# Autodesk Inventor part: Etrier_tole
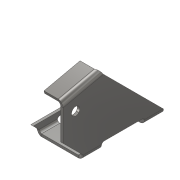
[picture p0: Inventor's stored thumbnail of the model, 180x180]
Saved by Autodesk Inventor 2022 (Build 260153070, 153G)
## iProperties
Created: 2018-06
Part Number: Etrier_tole
Material: Acier inoxydable
Document SubType Name: Tôle
Designer: Fabian Perrée
Density: 8 g/cm^3
Sheet Metal Rule: Par défaut_mm
Appearance: Semi-poli
Flat Pattern Width: 6.40181 cm
Flat Pattern Length: 9.4026 cm
Flat Pattern Area: 60.1936 cm^2
Sheet Metal Width: 64,018 mm
Sheet Metal Length: 94,026 mm
Sheet Metal Area: 6019,365 mm^2
Mass: 45.3586 g
Surface Area: 83.174 cm^2
Volume: 5.66982 cm^3
Author: Fabian Perrée
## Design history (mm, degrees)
node "Face1"
  sketch "Esquisse1"
    geometry: L1 (-12.5, 24)-(12.5, 24); L2 (12.5, 24)-(12.5, -24); L3 (12.5, -24)-(-12.5, -24); L4 (-12.5, -24)-(-12.5, 24); L5 (-12.5, 24)-(12.5, -24); L6 (12.5, 24)-(-12.5, -24); C1 r 3 at (0, 18.5); C2 r 3 at (0, -18.5); 3 further points
    constraints: 12 end point, 4 midpoint, 2 centre point, 2 parallel, 2 vertical alignment, 1 equal radius, 1 horizontal, 1 perpendicular
    dimensions: "d0" = 25 distance of L2.end L3.end; "d1" = 48 distance of L1.end L2.end; "d31" = 5.5 distance from line of L1 C1.centre (= d43); "d32" = 6 diameter of C1; "d43" = 5.5 distance from line of L3 C2.centre
node "Face2"
  sketch "Esquisse2"
    geometry: L1 (0, 0)-(0, 1.5) reference; L2 (48, 0)-(0, 0) reference; L3 (48, 0)-(48, 1.5) reference; L4 (0, 1.5)-(0, 3); L5 (0, 3)-(-12, 15); L6 (-12, 15)-(-12, 36.58); L7 (7, 3.333)-(7, -2.476); L8 (-12, 36.58)-(9.626, 41.374); L9 (48, 1.5)-(48, 3); L10 (48, 3)-(9.626, 41.374); C1 r 2.5 at (-4.5, 28); 2 further points
    constraints: 14 end point, 3 vertical, 1 centre point, 1 coincident, 1 parallel
    dimensions: "d3" = 3 distance from line of L2 L4.end; "d6" = 45 deg angle of L5 L6; "d7" = 28 distance from line of L2 point (-4.5, 28); "d8" = 7 distance between parallel lines of L4 L7; "d9" = 11.5 distance from line of point (-4.5, 28) L7; "d10" = 10 distance from line of point (-4.5, 28) L8; "d11" = 12.5 deg angle of L2 L8; "d12" = 3 distance from line of L2 L9.end; "d13" = 45 deg angle of L2 L10; "d14" = 5 diameter of C1; "d40" = 12 horizontal distance of L5.end L4.end
mirror "Symétrie1"
node "Bord tombé1"
sketch "Esquisse4"
  geometry: L1 (0, 0)-(48, 0) reference; L2 (11, 0)-(37, 0); L3 (37, 0)-(37, 2.5); L4 (35.5, 4)-(12.5, 4); L5 (11, 2.5)-(11, 0); L6 (2.5, 1.5)-(8.5, 1.5) reference; L7 (8.5, 0)-(2.5, 0) reference; L8 (0, 1.5)-(48, 1.5) reference; L9 (8.5, 0)-(2.5, 0) reference; L10 (45.5, 0)-(39.5, 0) reference; L11 (5.5, 0)-(5.5, -3.35); L12 (42.5, 0)-(42.5, -3.35); A1 r 1.5 centre (12.5, 2.5) between (12.5, 4) and (11, 2.5); A2 r 1.5 centre (35.5, 2.5) between (37, 2.5) and (35.5, 4); 3 further points
  constraints: 12 end point, 5 point on line, 4 point on circle, 4 tangent, 2 centre point, 2 midpoint, 2 parallel, 2 vertical, 1 equal radius, 1 horizontal, 1 perpendicular
  dimensions: "d35" = 1.5 radius of A1; "d36" = 4 distance between parallel lines of L2 L4; "d44" = 5.5 distance between parallel lines of L5 L11; "d45" = 5.5 distance between parallel lines of L3 L12 (= d44)
extrude "Extrusion1" cut sketch "Esquisse4" extent not by distance; stored distance "d37" = 10; taper "d38" = 0 deg
sketch "Esquisse5"
  geometry: L1 (43.946, -41.715)-(6.496, -41.715); L2 (6.496, -41.715)-(6.496, 46.634); L3 (6.496, 46.634)-(43.946, 46.634); L4 (43.946, 46.634)-(43.946, -41.715); 1 further point
  constraints: 8 end point, 2 parallel, 1 horizontal, 1 perpendicular
extrude "Extrusion2" cut sketch "Esquisse5" distance "d41" = 20; taper "d42" = 0 deg
node "Solide1"
feature "Plaque1" dims "d2" = 1.5 (= Epaisseur)
feature "Plaque2" dims "d2" = 1.5 (= Epaisseur), "d15" = 1.5 (= RayonPli), "d16" = 1.5 (= LargeurGrugeage), "d18" = 3 (= RestesMinimum)
feature "Pli1" dims "d2" = 1.5 (= Epaisseur), "d15" = 1.5 (= RayonPli), "d16" = 1.5 (= LargeurGrugeage), "d17" = 0.75 (= ProfondeurGrugeage), "d18" = 3 (= RestesMinimum), "d19" = 1.5 (= Rayondetransition), "JeuJointure" = 0.01
sketch "Esquisse3"
  geometry: L1 (11.5, 0)-(11.5, 22.151); L2 (11.5, 22.151)-(0, 22.151); 1 other entity
  constraints: 4 end point, 4 other
feature "Plaque3" dims "d2" = 1.5 (= Epaisseur), "d20" = 1.5 (= LargeurGrugeage), "d21" = 0.75 (= ProfondeurGrugeage), "d22" = 3 (= RestesMinimum), "d23" = 1.5 (= Rayondetransition), "d24" = 11.5, "d25" = 90 deg, "d26" = 1.5 (= RayonPli), "d27" = 6 (= TailleGrugeage), "d28" = 1.5 (= TailleJeu), "d29" = 1.5 (= TailleRayonJacobi), "JeuJointure" = 0.01
feature "Pli2" dims "d2" = 1.5 (= Epaisseur), "d20" = 1.5 (= LargeurGrugeage), "d21" = 0.75 (= ProfondeurGrugeage), "d22" = 3 (= RestesMinimum), "d23" = 1.5 (= Rayondetransition), "d24" = 11.5, "d25" = 90 deg, "d26" = 1.5 (= RayonPli), "JeuJointure" = 0.01
feature "Coin1" dims "d24" = 11.5, "d25" = 90 deg, "d27" = 6 (= TailleGrugeage), "d28" = 1.5 (= TailleJeu), "d29" = 1.5 (= TailleRayonJacobi)
node "Boucle projetée1"
feature "Définition1"
other parameters: "Epaisseur" = 1.5 (derived), "FacteurX" = 4.4, "RayonPli" = 1.5 (= Epaisseur), "LargeurGrugeage" = 1.5 (= Epaisseur), "ProfondeurGrugeage" = 0.75 (= 0.5 x Epaisseur), "TailleGrugeage" = 6 (= 4 x Epaisseur), "RestesMinimum" = 3 (= 2 x Epaisseur), "Rayondetransition" = 1.5 (= RayonPli), "TailleRayonJacobi" = 1.5 (= RayonPli), "TailleJeu" = 1.5 (= Epaisseur), "Epaisseur" = 1.5, "LargeurGrugeage" = 1.5, "ProfondeurGrugeage" = 0.75, "RayonPli" = 1.5, "Rayondetransition" = 1.5, "RestesMinimum" = 3, "TailleGrugeage" = 6, "TailleJeu" = 1.5, "TailleRayonJacobi" = 1.5
